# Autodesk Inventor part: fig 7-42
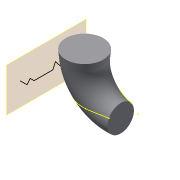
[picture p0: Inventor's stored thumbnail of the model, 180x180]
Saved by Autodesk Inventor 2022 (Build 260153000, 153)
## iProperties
Created: 2011-07
Part Number: fig 7-42
Material: Generic
Document SubType Name: Modeling
Designer: CadCim
Density: 1 g/cm^3
Appearance: Default
Author: CadCim
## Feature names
1. Sweep1
## Parameters: d0 = 5 deg, d1 = -14.75 mm, d2 = 0
